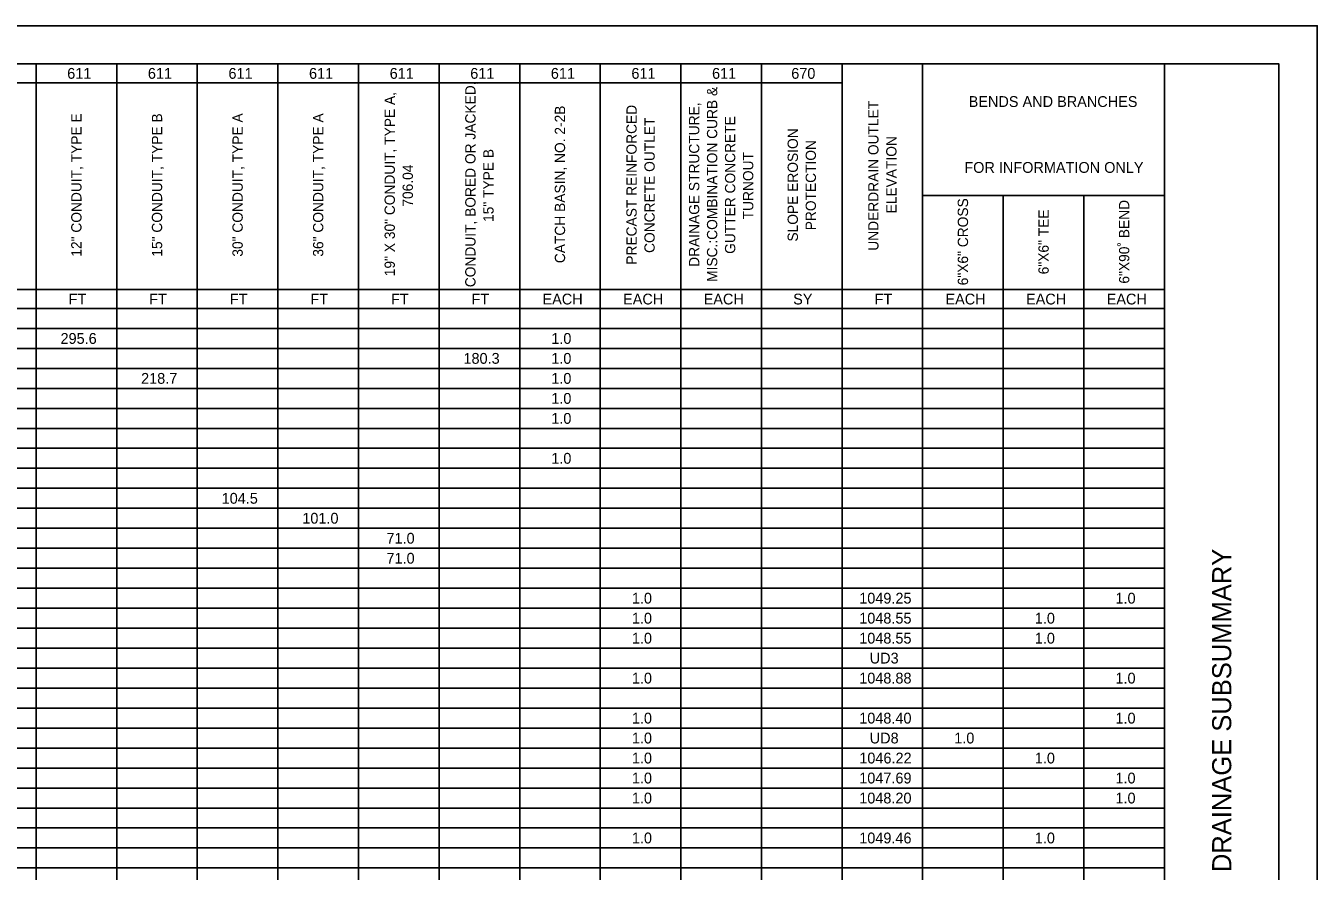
# Model space of a CAD drawing. Extents: x 0 to 34, y 0 to 22.
# Drawn here: x 17.09 to 34, y 10.93 to 22 of the extents above; entities that cross this region are included whole.
import ezdxf

# ---------------------------------------------------------------- set-up
doc = ezdxf.new("R2010")
doc.units = 0
for name, color, linetype in [('SH_Border', 7, 'Continuous'), ('SH_Cut_Line', 7, 'Continuous'), ('SH_Data', 7, 'Continuous'), ('SH_Text', 7, 'Continuous')]:
    doc.layers.add(name, color=color, linetype=linetype)

msp = doc.modelspace()

# ---------------------------------------------------------------- linework, layer by layer
at = {"layer": 'SH_Border'}
msp.add_line((32, 0.5), (32, 21.5), dxfattribs=at)
msp.add_lwpolyline([(1.5, 21.5), (33.5, 21.5), (33.5, 0.5), (1.5, 0.5)], close=True, dxfattribs=at)
at = {"layer": 'SH_Cut_Line'}
msp.add_lwpolyline([(0, 0), (34, 0), (34, 22), (0, 22)], close=True, dxfattribs=at)
at = {"layer": 'SH_Text'}
for p, q in [((1.5, 21.5), (32, 21.5)), ((17.226, 21.5), (17.226, 0.5)), ((18.282, 21.5), (18.282, 0.5)), ((19.337, 21.5), (19.337, 0.5)), ((20.392, 21.5), (20.392, 0.5)), ((21.447, 21.5), (21.447, 0.5)), ((22.503, 21.5), (22.503, 0.5)), ((23.558, 21.5), (23.558, 0.5)), ((24.613, 21.5), (24.613, 0.5)), ((25.668, 21.5), (25.668, 0.5)), ((26.724, 21.5), (26.724, 0.5)), ((27.779, 21.5), (27.779, 0.5)), ((28.834, 21.5), (28.834, 0.5)), ((32, 21.5), (32, 0.5)), ((7.729, 21.254), (27.779, 21.254)), ((28.834, 19.776), (32, 19.776)), ((29.889, 19.776), (29.889, 0.5)), ((30.945, 19.776), (30.945, 0.5)), ((7.729, 18.544), (32, 18.544)), ((1.5, 18.298), (32, 18.298)), ((1.5, 18.036), (32, 18.036)), ((1.5, 17.774), (32, 17.774)), ((1.5, 17.512), (32, 17.512)), ((1.5, 17.251), (32, 17.251)), ((1.5, 16.989), (32, 16.989)), ((1.5, 16.727), (32, 16.727)), ((1.5, 16.466), (32, 16.466)), ((1.5, 16.204), (32, 16.204)), ((1.5, 15.942), (32, 15.942)), ((1.5, 15.68), (32, 15.68)), ((1.5, 15.419), (32, 15.419)), ((10.895, 15.157), (32, 15.157)), ((1.5, 14.895), (32, 14.895)), ((1.5, 14.633), (32, 14.633)), ((1.5, 14.372), (32, 14.372)), ((1.5, 14.11), (32, 14.11)), ((1.5, 13.848), (32, 13.848)), ((1.5, 13.587), (32, 13.587)), ((1.5, 13.325), (32, 13.325)), ((1.5, 13.063), (32, 13.063)), ((1.5, 12.801), (32, 12.801)), ((1.5, 12.54), (32, 12.54)), ((1.5, 12.278), (32, 12.278)), ((1.5, 12.016), (32, 12.016)), ((1.5, 11.754), (32, 11.754)), ((1.5, 11.493), (32, 11.493)), ((1.5, 11.231), (32, 11.231)), ((1.5, 10.969), (32, 10.969))]:
    msp.add_line(p, q, dxfattribs=at)

# ---------------------------------------------------------------- texts
at = {"layer": 'SH_Data'}
msp.add_text('DRAINAGE SUBSUMMARY ', height=0.25, rotation=90, dxfattribs=at).set_placement((32.875, 10.915))
at = {"layer": 'SH_Text'}
for s, height, p in [('611', 0.1416, (17.634, 21.306)), ('611', 0.1416, (18.69, 21.306)), ('611', 0.1416, (19.745, 21.306)), ('611', 0.1416, (20.8, 21.306)), ('611', 0.1416, (21.856, 21.306)), ('611', 0.1416, (22.911, 21.306)), ('611', 0.1416, (23.966, 21.306)), ('611', 0.1416, (25.021, 21.306)), ('611', 0.1416, (26.077, 21.306)), ('670', 0.1416, (27.114, 21.306)), ('BENDS AND BRANCHES', 0.14164, (29.437, 20.937)), ('FOR INFORMATION ONLY', 0.14164, (29.38, 20.074)), ('FT', 0.1416, (17.652, 18.35)), ('FT', 0.1416, (18.707, 18.35)), ('FT', 0.1416, (19.763, 18.35)), ('FT', 0.1416, (20.818, 18.35)), ('FT', 0.1416, (21.873, 18.35)), ('FT', 0.1416, (22.928, 18.35)), ('EACH', 0.1416, (23.857, 18.35)), ('EACH', 0.1416, (24.912, 18.35)), ('EACH', 0.1416, (25.967, 18.35)), ('SY', 0.1416, (27.139, 18.35)), ('FT', 0.1416, (28.205, 18.35)), ('EACH', 0.1416, (29.133, 18.35)), ('EACH', 0.1416, (30.188, 18.35)), ('EACH', 0.1416, (31.244, 18.35)), ('295.6', 0.1416, (17.546, 17.834)), ('1.0', 0.1416, (23.972, 17.834)), ('180.3', 0.1416, (22.822, 17.573)), ('1.0', 0.1416, (23.972, 17.573)), ('218.7', 0.1416, (18.601, 17.311)), ('1.0', 0.1416, (23.972, 17.311)), ('1.0', 0.1416, (23.972, 17.049)), ('1.0', 0.1416, (23.972, 16.787)), ('1.0', 0.1416, (23.972, 16.264)), ('104.5', 0.1416, (19.656, 15.74)), ('101.0', 0.1416, (20.712, 15.479)), ('71.0', 0.1416, (21.814, 15.217)), ('71.0', 0.1416, (21.814, 14.955)), ('1.0', 0.1416, (25.027, 14.432)), ('1049.25', 0.1416, (28.004, 14.432)), ('1.0', 0.1416, (31.359, 14.432)), ('1.0', 0.1416, (25.027, 14.17)), ('1048.55', 0.1416, (28.004, 14.17)), ('1.0', 0.1416, (30.303, 14.17)), ('1.0', 0.1416, (25.027, 13.908)), ('1048.55', 0.1416, (28.004, 13.908)), ('1.0', 0.1416, (30.303, 13.908)), ('UD3', 0.1416, (28.141, 13.647)), ('1.0', 0.1416, (25.027, 13.385)), ('1048.88', 0.1416, (28.004, 13.385)), ('1.0', 0.1416, (31.359, 13.385)), ('1.0', 0.1416, (25.027, 12.861)), ('1048.40', 0.1416, (28.004, 12.861)), ('1.0', 0.1416, (31.359, 12.861)), ('1.0', 0.1416, (25.027, 12.6)), ('UD8', 0.1416, (28.141, 12.6)), ('1.0', 0.1416, (29.248, 12.6)), ('1.0', 0.1416, (25.027, 12.338)), ('1046.22', 0.1416, (28.005, 12.338)), ('1.0', 0.1416, (30.303, 12.338)), ('1.0', 0.1416, (25.027, 12.076)), ('1047.69', 0.1416, (28.004, 12.076)), ('1.0', 0.1416, (31.359, 12.076)), ('1.0', 0.1416, (25.027, 11.814)), ('1048.20', 0.1416, (28.004, 11.814)), ('1.0', 0.1416, (31.359, 11.814)), ('1.0', 0.1416, (25.027, 11.291)), ('1049.46', 0.1416, (28.004, 11.291)), ('1.0', 0.1416, (30.303, 11.291))]:
    msp.add_text(s, height=height, dxfattribs=at).set_placement(p)
for s, height, p in [('CONDUIT, BORED OR JACKED, ', 0.13484, (22.98, 18.576)), ('MISC.:COMBINATION CURB & ', 0.13484, (26.145, 18.646)), ('19" X 30" CONDUIT, TYPE A, ', 0.13484, (21.924, 18.72)), ('DRAINAGE STRUCTURE, ', 0.13484, (25.91, 18.843)), ('UNDERDRAIN OUTLET ', 0.13484, (28.256, 19.054)), ('12" CONDUIT, TYPE E', 0.13484, (17.821, 18.976)), ('15" CONDUIT, TYPE B', 0.13484, (18.877, 18.976)), ('30" CONDUIT, TYPE A', 0.13484, (19.932, 18.976)), ('36" CONDUIT, TYPE A', 0.13484, (20.987, 18.976)), ('CATCH BASIN, NO. 2-2B', 0.13484, (24.153, 18.891)), ('PRECAST REINFORCED ', 0.13484, (25.09, 18.871)), ('GUTTER CONCRETE ', 0.13484, (26.381, 19.013)), ('CONCRETE OUTLET', 0.13484, (25.326, 19.025)), ('SLOPE EROSION ', 0.13484, (27.201, 19.174)), ('PROTECTION', 0.1348, (27.437, 19.322)), ('ELEVATION', 0.1348, (28.492, 19.543)), ('15" TYPE B', 0.1348, (23.216, 19.431)), ('TURNOUT', 0.1348, (26.617, 19.465)), ('706.04', 0.1348, (22.16, 19.631)), ('6"X6" CROSS', 0.13484, (29.429, 18.601)), ('6"X90˚ BEND', 0.13484, (31.54, 18.623)), ('6"X6" TEE', 0.1348, (30.485, 18.745))]:
    msp.add_text(s, height=height, rotation=90, dxfattribs=at).set_placement(p)

doc.saveas('drawing.dxf')
